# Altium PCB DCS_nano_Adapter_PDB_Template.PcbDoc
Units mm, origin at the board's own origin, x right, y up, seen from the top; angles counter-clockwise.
Board outline 119.55 x 51 mm, 6 copper layers (Top Layer, Layer 2, Layer 3, Layer 4, Layer 5, Bottom Layer), stack 1.74 mm thick; 48 components, 201 nets, 674 pads, 10 vias.
Unrouted connection lines stored in the file: 350.
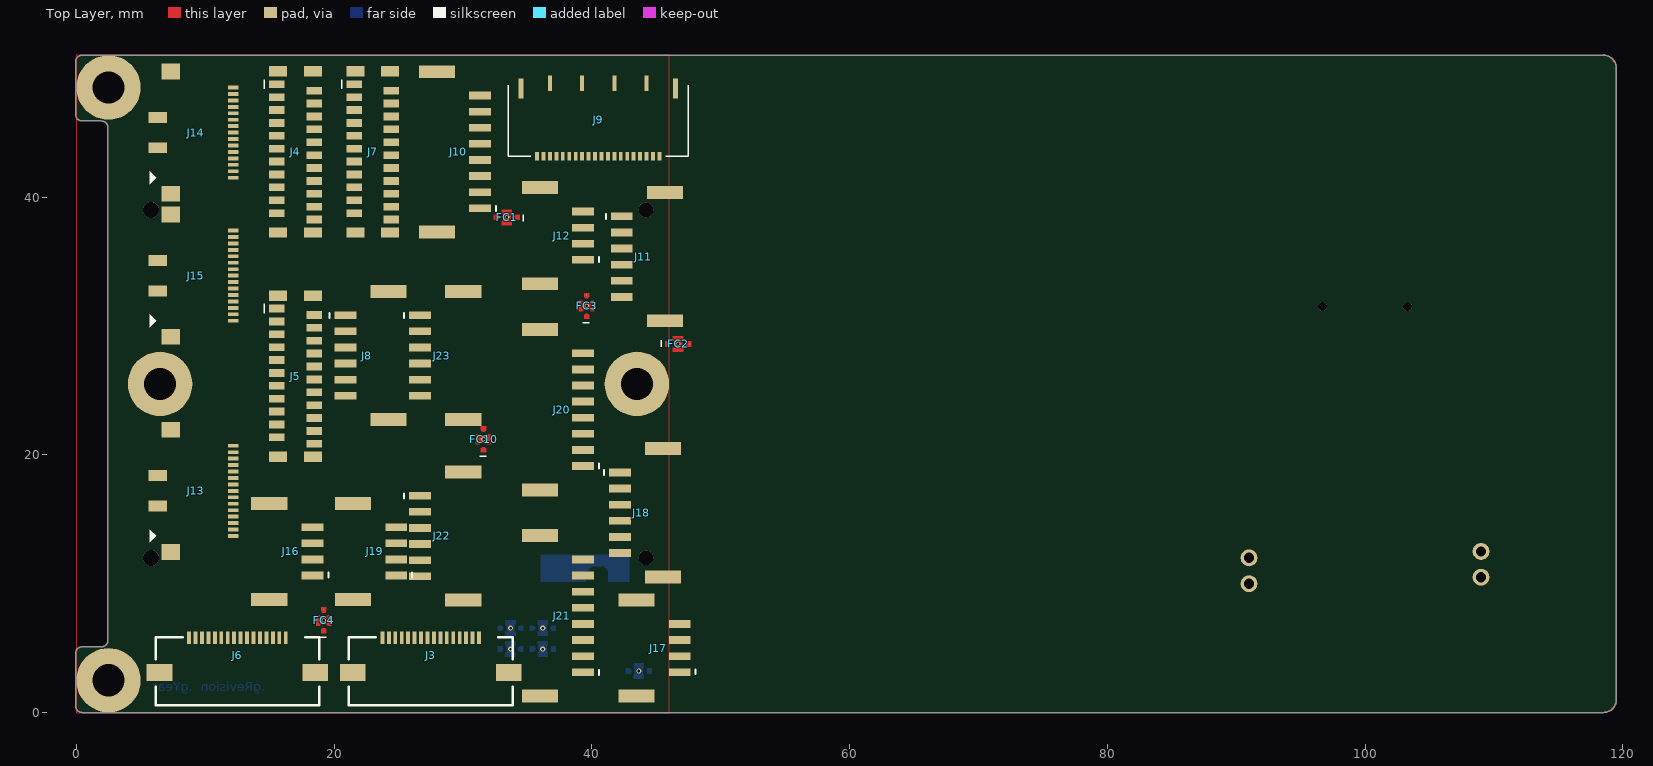
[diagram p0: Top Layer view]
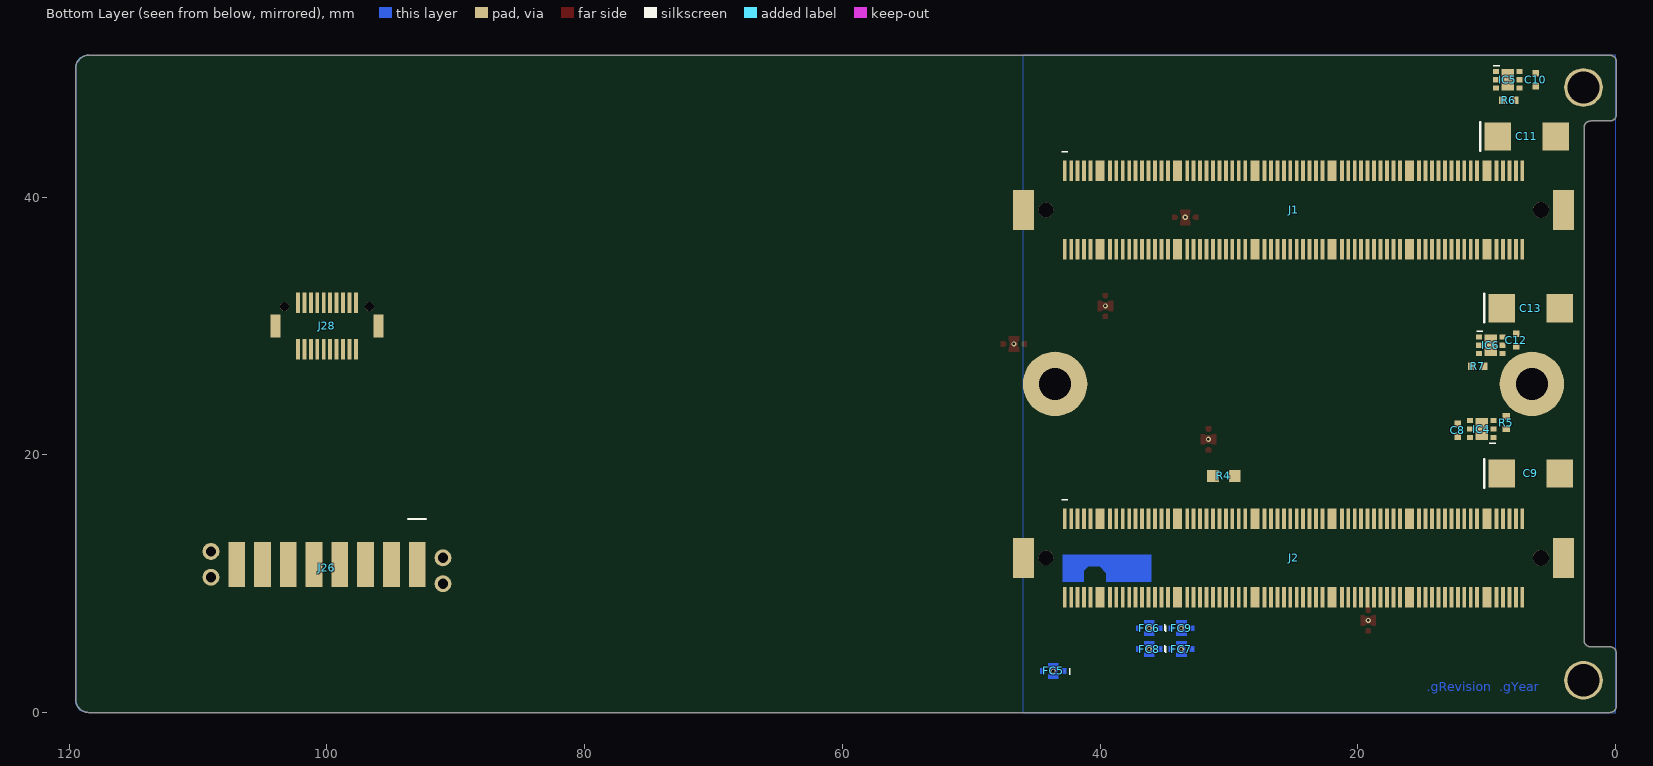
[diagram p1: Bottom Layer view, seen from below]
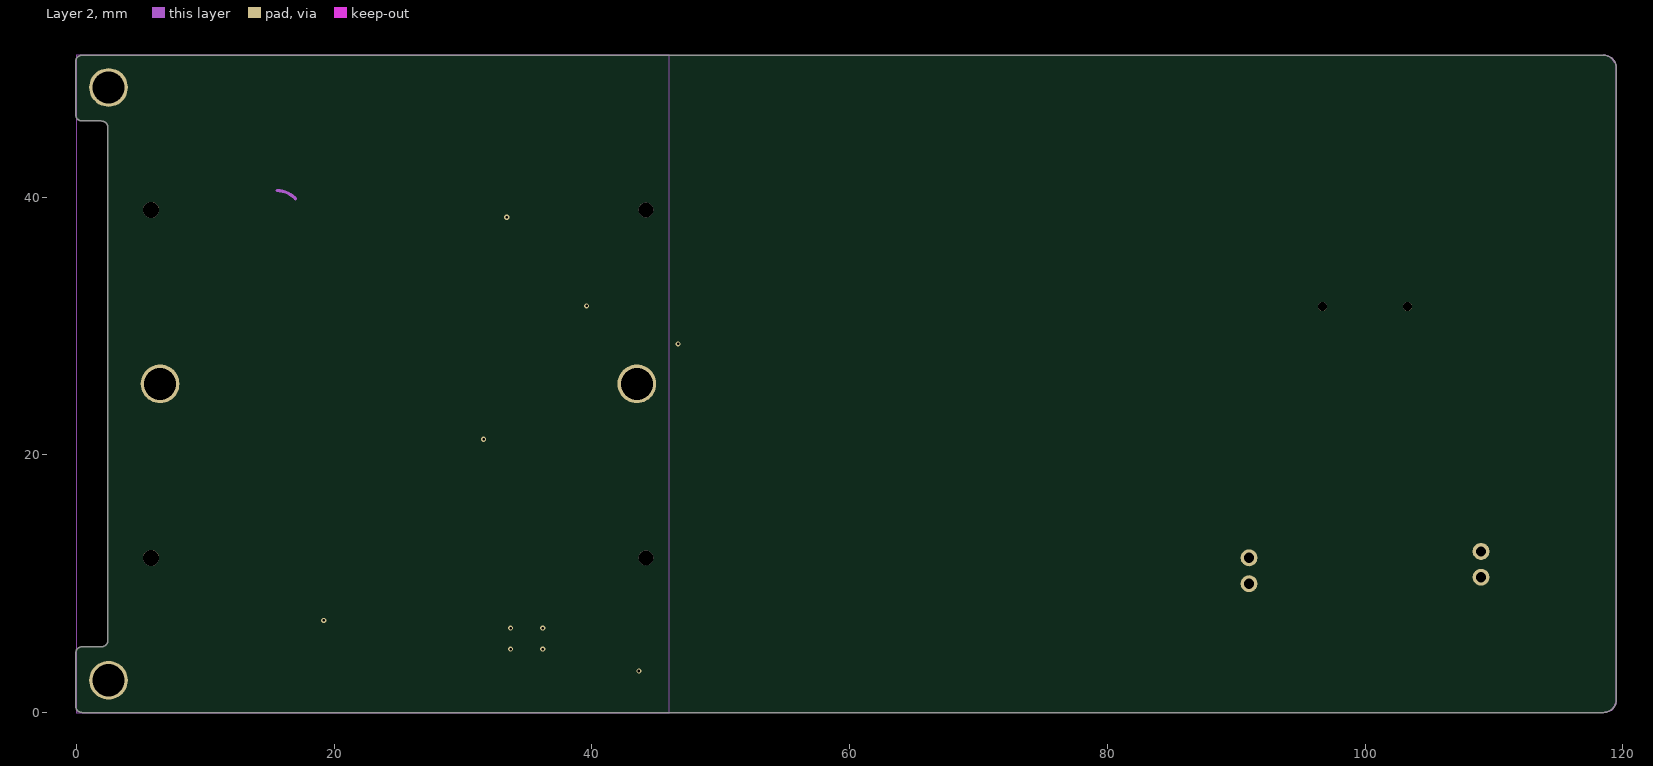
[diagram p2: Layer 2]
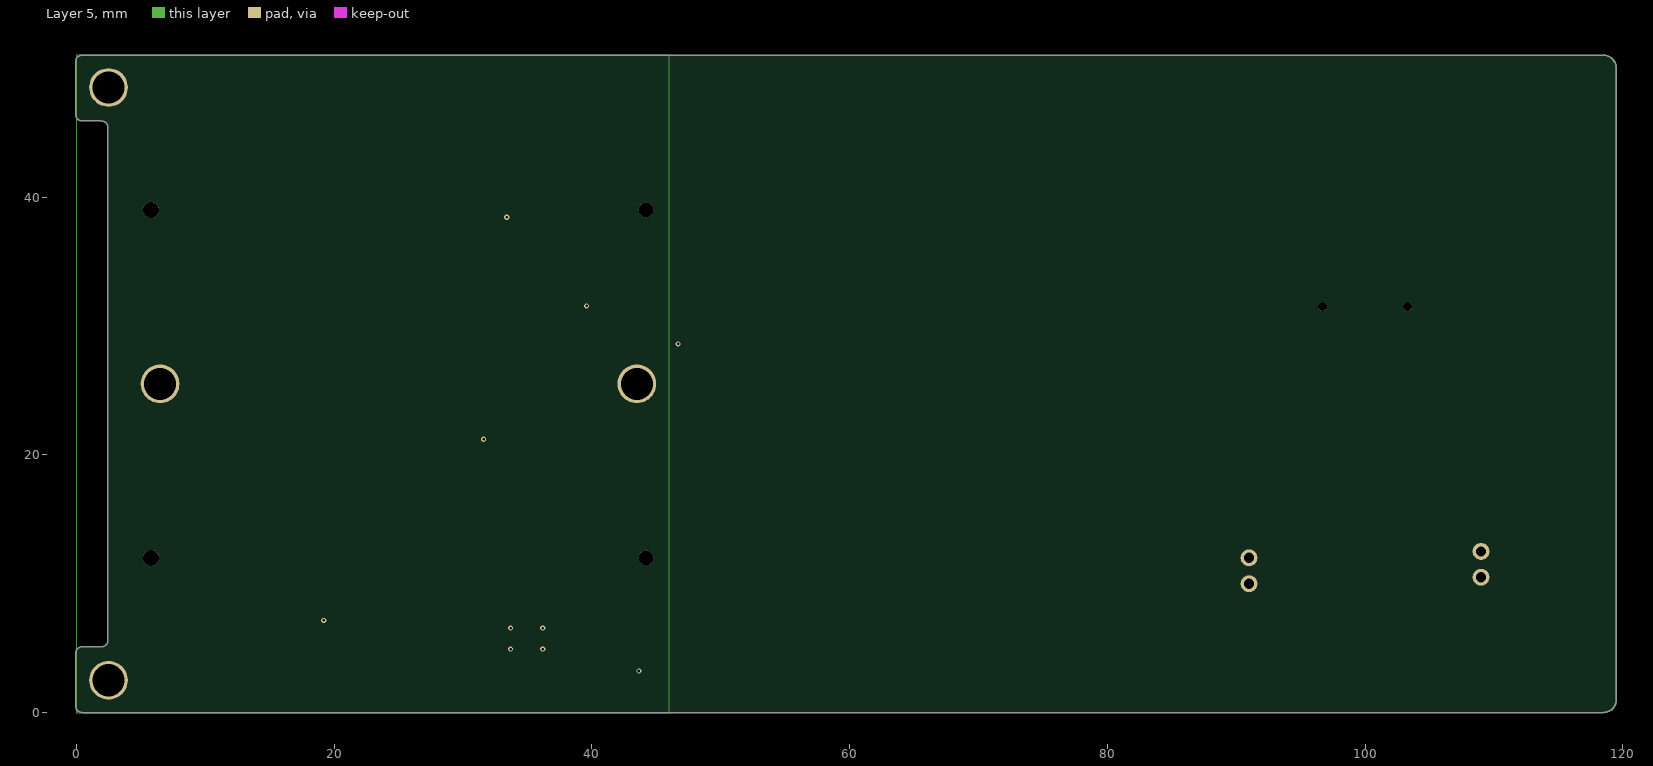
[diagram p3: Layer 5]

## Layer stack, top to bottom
Top Solder: solder mask 0.0102, Solder Resist, Dk 3.5
Top Layer: signal copper 0.035
Dielectric 2: prepreg 0.11, PP, Dk 4.29
Layer 2: signal copper 0.035
Dielectric 4: core 0.6, FR-4, Dk 4.3
Layer 3: signal copper 0.035
Dielectric 1: prepreg 0.11, PP, Dk 4.29
Layer 4: signal copper 0.035
Dielectric 5: core 0.6, FR-4, Dk 4.3
Layer 5: signal copper 0.035
Dielectric 3: prepreg 0.11, PP, Dk 4.29
Bottom Layer: signal copper 0.035
Bottom Solder: solder mask 0.0102, Solder Resist, Dk 3.5

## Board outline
0.45,0 cw(c0.45,0.5) -0.05,0.5 -0.05,4.6 cw(c0.45,4.6) 0.45,5.1 1.95,5.1 ccw(c1.95,5.6) 2.45,5.6 2.45,5.598 2.45,45.4 ccw(c1.95,45.4) 1.95,45.9 0.45,45.9 cw(c0.45,46.4) -0.05,46.4 -0.05,50.5 cw(c0.45,50.5) 0.45,51 1.95,51 118.5,51 cw(c118.5,50) 119.5,50 119.5,1 cw(c118.5,1) 118.5,0

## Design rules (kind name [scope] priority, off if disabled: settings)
Clearance Clearance_GND [InNet('GND')] p1: gap=0.127 ignorepadtopadclearanceinfootprint=TRUE except(0.3: Via-Poly; 0.5: Arc-Poly Track-Poly SMDPad-Poly THPad-Poly Fill-Poly Poly-Poly)
Clearance Clearance_DEfault [All] p2: gap=0.127 ignorepadtopadclearanceinfootprint=TRUE except(0.2: Arc-Poly Track-Poly SMDPad-Poly THPad-Poly Via-Poly Fill-Poly Poly-Poly)
ComponentClearance 3D [OnLayer('Mechanical1')] p1: gap=0 collisioncheckmode=3 verticalgap=0 showdistances=FALSE
ComponentClearance ComponentClearance_HasFootprint('HRS_FX10A-120S/12-SV') [HasFootprint('HRS_FX10A-120S/12-SV')] p2: gap=0 collisioncheckmode=3 verticalgap=0 showdistances=FALSE
ComponentClearance [All] p3: gap=0.254 collisioncheckmode=3 verticalgap=0.254 showdistances=FALSE
DiffPairsRouting 90Ohm_Diffs [InDifferentialPairClass('90OHM_NETS')] p1: maxlimit=0.254 minlimit=0.203 mostfreqgap=0.254 toplayer_mingap=0.24 toplayer_maxgap=0.24 toplayer_prefgap=0.24 toplayer_minwidth=0.2 toplayer_maxwidth=0.2 toplayer_prefwidth=0.2 midlayer3_maxgap=0.203 midlayer3_prefgap=0.203 midlayer3_minwidth=0.127 midlayer3_maxwidth=0.127 midlayer3_prefwidth=0.127 bottomlayer_mingap=0.25 bottomlayer_maxgap=0.25 bottomlayer_prefgap=0.25 bottomlayer_minwidth=0.2 bottomlayer_maxwidth=0.2 bottomlayer_prefwidth=0.2 impedanceprofiledriven=TRUE impedanceprofileid={C9F50B21-FE22-43FD-958F-A5668B17B2B7} impedanceprofilevalue=90.000000 maxuncoupledlength=12.7
DiffPairsRouting 95Ohm_Diffs [InDifferentialPairClass('95OHM_NETS')] p2: maxlimit=0.3 minlimit=0.239 mostfreqgap=0.295 toplayer_maxgap=0.239 toplayer_prefgap=0.239 toplayer_minwidth=0.18 toplayer_maxwidth=0.18 toplayer_prefwidth=0.18 midlayer3_mingap=0.295 midlayer3_maxgap=0.295 midlayer3_minwidth=0.127 midlayer3_maxwidth=0.127 midlayer3_prefwidth=0.127 bottomlayer_maxgap=0.239 bottomlayer_prefgap=0.239 bottomlayer_minwidth=0.18 bottomlayer_maxwidth=0.18 bottomlayer_prefwidth=0.18 impedanceprofiledriven=TRUE impedanceprofileid={FDBBF226-2248-4E26-9AAD-8D10470732B8} impedanceprofilevalue=95.000000 maxuncoupledlength=12.7
MatchedLengths CSI_INTRA [InxSignalClass('xSignals_CSI')] p1: tolerance=0.07 checknetsindiffpair=TRUE checkdiffpairvsdiffpair=FALSE checkxsignals=FALSE checkothers=FALSE
MatchedLengths ETH_INTRA [InxSignalClass('xSignals_ETH')] p2: tolerance=0.05 checknetsindiffpair=TRUE checkdiffpairvsdiffpair=FALSE checkxsignals=FALSE checkothers=FALSE
MatchedLengths PCIE_INTRA [InxSignalClass('xSignals_PCIE')] p3: tolerance=0.04 checknetsindiffpair=TRUE checkdiffpairvsdiffpair=FALSE checkxsignals=FALSE checkothers=FALSE
MatchedLengths USB3_INTRA [InxSignalClass('xSignals_USB3')] p4: tolerance=0.07 checknetsindiffpair=TRUE checkdiffpairvsdiffpair=FALSE checkxsignals=FALSE checkothers=FALSE
MatchedLengths USB2_INTRA [InxSignalClass('xSignals_USB2')] p5: tolerance=0.4 checknetsindiffpair=TRUE checkdiffpairvsdiffpair=FALSE checkxsignals=FALSE checkothers=FALSE
MatchedLengths CSI0_GROUP [InxSignalClass('xSIgnals_CSI0')] p6: tolerance=0.5 checknetsindiffpair=FALSE checkdiffpairvsdiffpair=TRUE checkxsignals=TRUE checkothers=TRUE
MatchedLengths CSI1_GROUP [InxSignalClass('xSIgnals_CSI1')] p7: tolerance=0.5 checknetsindiffpair=FALSE checkdiffpairvsdiffpair=TRUE checkxsignals=TRUE checkothers=TRUE
MatchedLengths CSI2_3_GROUP [InxSignalClass('xSIgnals_CSI_2_3')] p8: tolerance=0.5 checknetsindiffpair=FALSE checkdiffpairvsdiffpair=TRUE checkxsignals=TRUE checkothers=TRUE
MinimumSolderMaskSliver [All] p1: minsoldermaskwidth=0.2
PolygonConnect Polygon_GND_connect [InNet('GND')] p1: thpad.connectstyle=Relief thpad.reliefconductorwidth=0.254 thpad.reliefentries=4 thpad.polygonreliefangle="90 Angle" thpad.airgapwidth=0.254 smdpad.connectstyle=Relief smdpad.reliefconductorwidth=0.2 smdpad.reliefentries=4 smdpad.polygonreliefangle="90 Angle" smdpad.airgapwidth=0.2 via.connectstyle=Direct via.reliefconductorwidth=0.254 via.reliefentries=4 via.polygonreliefangle="90 Angle" via.airgapwidth=0.254
PolygonConnect [All] p2: thpad.connectstyle=Relief thpad.reliefconductorwidth=0.254 thpad.reliefentries=4 thpad.polygonreliefangle="90 Angle" thpad.airgapwidth=0.254 smdpad.connectstyle=Direct smdpad.reliefconductorwidth=0.254 smdpad.reliefentries=4 smdpad.polygonreliefangle="90 Angle" smdpad.airgapwidth=0.254 via.connectstyle=Direct via.reliefconductorwidth=0.254 via.reliefentries=4 via.polygonreliefangle="90 Angle" via.airgapwidth=0.254
RoutingVias [All] p1: holewidth=0.2 width=0.4 viastyle="Through Hole" minholewidth=0.2 minwidth=0.4 maxholewidth=0.6 maxwidth=0.9
SilkToSilkClearance [All] p1: silktosilkclearance=0
SilkToSolderMaskClearance [IsPad] p1: minsilkscreentomaskgap=0.01 clearancetoexposedcopper=TRUE
SolderMaskExpansion [All] p1: expansion=0.102 istentingtop=FALSE
SupplyNets "Schematic Supply Nets_7" [InNet('5V_CRUCIAL')] p1: voltage=0.000
SupplyNets "Schematic Supply Nets_6" [InNet('5V')] p2: voltage=0.000
SupplyNets "Schematic Supply Nets_5" [InNet('5V_SAFETY')] p3: voltage=0.000
SupplyNets "Schematic Supply Nets_4" [InNet('3V3')] p4: voltage=0.000
SupplyNets "Schematic Supply Nets_3" [InNet('3V3_SOM')] p5: voltage=0.000
SupplyNets "Schematic Supply Nets_2" [InNet('GND')] p6: voltage=0.000
SupplyNets "Schematic Supply Nets_1" [InNet('5V_PERIPH')] p7: voltage=0.000
SupplyNets "Schematic Supply Nets" [InNet('VDD_SOM')] p8: voltage=0.000
Width [All] p1: maxlimit=0.8 minlimit=0.127 preferedwidth=0.254
25 further rules are at their usual default settings.

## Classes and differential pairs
component class U_PDB_Related_Connectors: J26 J28
differential pair class 95OHM_NETS: ETH1A ETH1B ETH1C ETH1D ETH2A ETH2B ETH2C ETH2D
differential pair class 90OHM_NETS: CSI0_CLK CSI0_D0 CSI0_D1 CSI1_CLK CSI1_D0 CSI1_D1 CSI2_CLK CSI2_D0 CSI2_D1 CSI3_CLK CSI3_D0 CSI3_D1 PCIE_AD_CLK PCIE_AD_RX PCIE_AD_TX USB_0 USB_1 USB_2 USBSS0_RX USBSS0_TX USBSS1_RX USBSS1_TX USBSS2_RX USBSS2_TX
net class USB_NETS: USB_0_N USB_0_P USB_1_N USB_1_P USB_2_N USB_2_P USBSS0_RX_N USBSS0_RX_P USBSS0_TX_N USBSS0_TX_P USBSS1_RX_N USBSS1_RX_P USBSS1_TX_N USBSS1_TX_P USBSS2_RX_N USBSS2_RX_P USBSS2_TX_N USBSS2_TX_P
net class PCIE_NETS: PCIE_AD_CLK_N PCIE_AD_CLK_P PCIE_AD_RX_N PCIE_AD_RX_P PCIE_AD_TX_N PCIE_AD_TX_P
net class ETH_NETS: ETH1A_N ETH1A_P ETH1B_N ETH1B_P ETH1C_N ETH1C_P ETH1D_N ETH1D_P ETH2A_N ETH2A_P ETH2B_N ETH2B_P ETH2C_N ETH2C_P ETH2D_N ETH2D_P
net class CSI_NETS: CSI0_CLK_N CSI0_CLK_P CSI0_D0_N CSI0_D0_P CSI0_D1_N CSI0_D1_P CSI1_CLK_N CSI1_CLK_P CSI1_D0_N CSI1_D0_P CSI1_D1_N CSI1_D1_P CSI2_CLK_N CSI2_CLK_P CSI2_D0_N CSI2_D0_P CSI2_D1_N CSI2_D1_P CSI3_CLK_N CSI3_CLK_P CSI3_D0_N CSI3_D0_P CSI3_D1_N CSI3_D1_P
net class CAN_NETS: CAN_1_N CAN_1_P CAN_2_N CAN_2_P CAN_3_N CAN_3_P CAN_JET_N CAN_JET_P
component class U_Jetson_Connectors: C8 C9 C10 C11 C12 C13 FC1 FC2 FC3 IC4 IC5 IC6 J3 J4 J5 J6 J7 J8 J9 J10 J11 J12 J13 J14 J15 R4 R5 R6 R7
component class U_FMU_related_Connectors: FC4 FC5 FC6 FC7 FC8 FC9 FC10 J16 J17 J18 J19 J20 J21 J22 J23
component class U_Adapter_B2B_Connectors: J1 J2
differential pair USBSS2_TX: +USBSS2_TX_P -USBSS2_TX_N
differential pair USBSS2_RX: +USBSS2_RX_P -USBSS2_RX_N
differential pair USBSS1_TX: +USBSS1_TX_P -USBSS1_TX_N
differential pair USBSS1_RX: +USBSS1_RX_P -USBSS1_RX_N
differential pair USBSS0_TX: +USBSS0_TX_P -USBSS0_TX_N
differential pair USBSS0_RX: +USBSS0_RX_P -USBSS0_RX_N
differential pair USB_2: +USB_2_P -USB_2_N
differential pair USB_1: +USB_1_P -USB_1_N
differential pair USB_0: +USB_0_P -USB_0_N
differential pair PCIE_AD_TX: +PCIE_AD_TX_P -PCIE_AD_TX_N
differential pair PCIE_AD_RX: +PCIE_AD_RX_P -PCIE_AD_RX_N
differential pair PCIE_AD_CLK: +PCIE_AD_CLK_P -PCIE_AD_CLK_N
differential pair ETH2D: +ETH2D_P -ETH2D_N
differential pair ETH2C: +ETH2C_P -ETH2C_N
differential pair ETH2B: +ETH2B_P -ETH2B_N
differential pair ETH2A: +ETH2A_P -ETH2A_N
differential pair ETH1D: +ETH1D_P -ETH1D_N
differential pair ETH1C: +ETH1C_P -ETH1C_N
differential pair ETH1B: +ETH1B_P -ETH1B_N
differential pair ETH1A: +ETH1A_P -ETH1A_N
differential pair CSI3_D1: +CSI3_D1_P -CSI3_D1_N
differential pair CSI3_D0: +CSI3_D0_P -CSI3_D0_N
differential pair CSI3_CLK: +CSI3_CLK_P -CSI3_CLK_N
differential pair CSI2_D1: +CSI2_D1_P -CSI2_D1_N
differential pair CSI2_D0: +CSI2_D0_P -CSI2_D0_N
differential pair CSI2_CLK: +CSI2_CLK_P -CSI2_CLK_N
differential pair CSI1_D1: +CSI1_D1_P -CSI1_D1_N
differential pair CSI1_D0: +CSI1_D0_P -CSI1_D0_N
differential pair CSI1_CLK: +CSI1_CLK_P -CSI1_CLK_N
differential pair CSI0_D1: +CSI0_D1_P -CSI0_D1_N
differential pair CSI0_D0: +CSI0_D0_P -CSI0_D0_N
differential pair CSI0_CLK: +CSI0_CLK_P -CSI0_CLK_N
differential pair CAN_JET: +CAN_JET_P -CAN_JET_N
differential pair CAN_3: +CAN_3_P -CAN_3_N
differential pair CAN_2: +CAN_2_P -CAN_2_N
differential pair CAN_1: +CAN_1_P -CAN_1_N

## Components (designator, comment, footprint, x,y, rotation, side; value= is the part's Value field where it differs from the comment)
C8 "AV_CAP_0402_1uF_25V" C0402 12.25,21.9 r90 bottom value=1uF
C9 "AV_CAP_2312_TANTAL_220uF_25V" AVX-TAJ-C-2_L 6.6,18.55 r180 bottom value=220uF
C10 "AV_CAP_0402_1uF_25V" C0402 6.2,49.1 r270 bottom value=1uF
C11 "AV_CAP_2312_TANTAL_220uF_25V" AVX-TAJ-C-2_L 6.9,44.7 r180 bottom value=220uF
C12 "AV_CAP_0402_1uF_25V" C0402 7.7,28.9 r270 bottom value=1uF
C13 "AV_CAP_2312_TANTAL_220uF_25V" AVX-TAJ-C-2_L 6.6,31.375 r180 bottom value=220uF
FC1 "CMP-023-000005-1" NFM18PS105R0J3D 33.4,38.425 r180 top
FC2 "CMP-023-000005-1" NFM18PS105R0J3D 46.7,28.6 r0 top
FC3 "CMP-023-000005-1" NFM18PS105R0J3D 39.6,31.55 r90 top
FC4 "CMP-023-000005-1" NFM18PS105R0J3D 19.2,7.15 r90 top
FC5 "CMP-023-000005-1" NFM18PS105R0J3D 43.65,3.225 r0 bottom
FC6 "CMP-023-000005-1" NFM18PS105R0J3D 36.2,6.55 r0 bottom
FC7 "CMP-023-000005-1" NFM18PS105R0J3D 33.7,4.925 r180 bottom
FC8 "CMP-023-000005-1" NFM18PS105R0J3D 36.2,4.925 r0 bottom
FC9 "CMP-023-000005-1" NFM18PS105R0J3D 33.7,6.55 r180 bottom
FC10 "CMP-023-000005-1" NFM18PS105R0J3D 31.6,21.2 r90 top
IC4 "CMP-045-000045-1" SON65P200X200X55-7N 10.4,22 r0 bottom
IC5 "CMP-045-000045-1" SON65P200X200X55-7N 8.385,49.1 r180 bottom
IC6 "CMP-045-000045-1" SON65P200X200X55-7N 9.7,28.5 r180 bottom
J1 "CMP-011-000018-1" HRS_FX10A-120S/12-SV 25,39 r180 bottom locked
J2 "CMP-011-000018-1" HRS_FX10A-120S/12-SV 25,12 r180 bottom locked
J3 "CMP-008-000009-1" 5051101692 27.5,3.2 r0 top locked
J4 "CMP-008-000016-1" 5019512210 17,43.5 r270 top
J5 "CMP-008-000016-1" 5019512210 17,26.1 r270 top
J6 "CMP-008-000009-1" 5051101692 12.5,3.2 r0 top locked
J7 "CMP-008-000016-1" 5019512210 23,43.5 r270 top
J8 "BM06B-GHS-TBT(LF)(SN)" FP-BM06B-GHS-TBT_LF_SN-MFG 23.2,27.7 r270 top
J9 "FH41-20S-0.5SH_05_" FH4120S05SH05 40.5,46 r180 top
J10 "BM08B-GHS-TBT(LF)(SN)" FP-BM08B-GHS-TBT_LF_SN-MFG 29,43.5 r270 top
J11 "BM06B-GHS-TBT(LF)(SN)" FP-BM06B-GHS-TBT_LF_SN-MFG 44.65,35.375 r270 top
J12 "BM04B-GHS-TBT(LF)(SN)" FP-BM04B-GHS-TBT_LF_SN-MFG 37,37 r270 top
J13 "CMP-009-000000-1" 5022441530 9.4,17.2 r270 top
J14 "CMP-009-000000-1" 5022441530 9.4,45 r270 top
J15 "CMP-009-000000-1" 5022441530 9.4,33.9 r270 top
J16 "BM04B-GHS-TBT(LF)(SN)" FP-BM04B-GHS-TBT_LF_SN-MFG 16,12.5 r270 top
J17 "BM04B-GHS-TBT(LF)(SN)" FP-BM04B-GHS-TBT_LF_SN-MFG 44.5,5 r270 top
J18 "BM06B-GHS-TBT(LF)(SN)" FP-BM06B-GHS-TBT_LF_SN-MFG 44.5,15.5 r270 top
J19 "BM04B-GHS-TBT(LF)(SN)" FP-BM04B-GHS-TBT_LF_SN-MFG 22.5,12.5 r270 top
J20 "BM08B-GHS-TBT(LF)(SN)" FP-BM08B-GHS-TBT_LF_SN-MFG 37,23.5 r270 top
J21 "BM08B-GHS-TBT(LF)(SN)" FP-BM08B-GHS-TBT_LF_SN-MFG 37,7.5 r270 top
J22 "BM06B-GHS-TBT(LF)(SN)" FP-BM06B-GHS-TBT_LF_SN-MFG 29,13.7 r270 top
J23 "BM06B-GHS-TBT(LF)(SN)" FP-BM06B-GHS-TBT_LF_SN-MFG 29,27.7 r270 top
J26 "UMPS-08-03.5-G-V-S-W-TR" SAMTEC_UMPS-08-03.5-G-V-S-W-TR 100,11.5 r0 bottom locked
J28 "CMP-011-000020-1" 10132797-025100LF 100,30 r180 bottom locked
R4 "AV_RES_0603_120R_1%" R0603 30.4,18.356 r0 bottom value=120R
R5 "AV_RES_0402_18k_1%" R0402 8.5,22.5 r270 bottom value=18k
R6 "AV_RES_0402_18k_1%" R0402 8.3,47.5 r0 bottom value=18k
R7 "AV_RES_0402_18k_1%" R0402 10.7,26.875 r0 bottom value=18k

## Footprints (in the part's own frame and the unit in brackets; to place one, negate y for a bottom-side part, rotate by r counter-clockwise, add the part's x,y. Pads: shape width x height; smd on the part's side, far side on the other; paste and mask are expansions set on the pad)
10132797-025100LF [mm]
  rect 0.3x1.6 smd: 1(2.25,1.8) 2(1.75,1.8) 3(1.25,1.8) 4(0.75,1.8) 5(0.25,1.8) 6(-0.25,1.8) 7(-0.75,1.8) 8(-1.25,1.8) 9(-1.75,1.8) 10(-2.25,1.8) 11(-2.25,-1.8) 12(-1.75,-1.8) 13(-1.25,-1.8) 14(-0.75,-1.8) 15(-0.25,-1.8) 16(0.25,-1.8) 17(0.75,-1.8) 18(1.25,-1.8) 19(1.75,-1.8) 20(2.25,-1.8)
  round 0.7 hole 0.7 unplated: LOC(-3.3,1.5) LOC(3.3,1.5)
  rect 0.8x1.8 smd: MP(-4,0) MP(4,0)
  body extent -4,-2.29 4,2.31, height 4.3
5019512210 [mm]
  rect 0.6x1.2 smd: 1(-5.25,-1.45) 2(-4.75,1.45) 3(-4.25,-1.45) 4(-3.75,1.45) 5(-3.25,-1.45) 6(-2.75,1.45) 7(-2.25,-1.45) 8(-1.75,1.45) 9(-1.25,-1.45) 10(-0.75,1.45) 11(-0.25,-1.45) 12(0.25,1.45) 13(0.75,-1.45) 14(1.25,1.45) 15(1.75,-1.45) 16(2.25,1.45) 17(2.75,-1.45) 18(3.25,1.45) 19(3.75,-1.45) 20(4.25,1.45) 21(4.75,-1.45) 22(5.25,1.45)
  rect 0.8x1.4 smd: MP1(-6.25,-1.35) MP2(6.25,-1.35) MP3(6.25,1.35) MP4(-6.25,1.35)
  silkscreen extent -5.6,-2.4 -4.9,-2.4, body extent -6.9,-2.05 6.9,2.08, height 4.59
5022441530 [mil] "Molex LVDS conn, 15pin, 0.5mm pitch"
  rect 11.81x31.5 smd: 1(-137.8,109.45) 2(-118.11,109.45) 3(-98.43,109.45) 4(-78.74,109.45) 5(-59.06,109.45) 6(-39.37,109.45) 7(-19.69,109.45) 8(0,109.45) 9(19.69,109.45) 10(39.37,109.45) 11(59.06,109.45) 12(78.74,109.45) 13(98.43,109.45) 14(118.11,109.45) 15(137.8,109.45)
  rect 48.03x55.12 smd: MP1(-186.61,-81.5) MP2(186.61,-81.5)
  rect 33.46x55.12 smd: MP3(-46.26,-121.26) MP4(46.26,-121.26)
  silkscreen extent 118,-146 157,-126, body extent -199,-138 199,116, height 92
5051101692 [mm]
  rect 0.3x1 smd: 1(-3.75,2.6) 2(-3.25,2.6) 3(-2.75,2.6) 4(-2.25,2.6) 5(-1.75,2.6) 6(-1.25,2.6) 7(-0.75,2.6) 8(-0.25,2.6) 9(0.25,2.6) 10(0.75,2.6) 11(1.25,2.6) 12(1.75,2.6) 13(2.25,2.6) 14(2.75,2.6) 15(3.25,2.6) 16(3.75,2.6)
  rect 2x1.3 smd: MP1(-6.05,-0.1) MP2(6.05,-0.1)
  silkscreen extent -6.35,-2.65 6.35,2.65, body extent -6.75,-2.43 6.75,2.87, height 1.9
AVX-TAJ-C-2_L [mm] "Molded Capacitor, 2-Leads, Body 6.2x3.4mm, IPC High Density"
  rect 2.05x2.2 smd: +(-2.25,0) -(2.25,0)
  silkscreen extent -3.6,-1.1 -3.6,1.1, body extent -3.32,-1.7 3.32,1.7, height 2.8
C0402 [mm]
  rect 0.5x0.5 smd: 1(-0.5,0) 2(0.5,0)
  body extent -0.5,-0.25 0.5,0.25, height 0.5
FH4120S05SH05 [mm]
  rect 0.3x0.65 smd: 1(-4.75,2.838) 2(-4.25,2.838) 3(-3.75,2.838) 4(-3.25,2.838) 5(-2.75,2.838) 6(-2.25,2.838) 7(-1.75,2.838) 8(-1.25,2.838) 9(-0.75,2.838) 10(-0.25,2.838) 11(0.25,2.838) 12(0.75,2.838) 13(1.25,2.838) 14(1.75,2.838) 15(2.25,2.838) 16(2.75,2.838) 17(3.25,2.838) 18(3.75,2.838) 19(4.25,2.838) 20(4.75,2.838)
  rect 0.4x1.55 smd: MP1(-6,-2.412) MP2(6,-2.412)
  rect 0.3x1.2 smd: MP3(-3.75,-2.837) MP4(1.25,-2.837) MP5(3.75,-2.837) MP6(-1.25,-2.837)
  silkscreen extent -7,-2.66 7,2.84, body extent -7,-3.25 7,3, height 2.48
FP-BM04B-GHS-TBT_LF_SN-MFG [mm]
  rect 0.6x1.7 smd paste+0 mask+0: 1(1.875,2.325) 2(0.625,2.325) 3(-0.625,2.325) 4(-1.875,2.325)
  rect 1x2.8 smd paste+0 mask+0: GND(-3.725,-1.025) GND(3.725,-1.025)
  silkscreen extent 1.65,3.56 2.03,3.56, body extent -4.33,-2.52 4.33,3.27, height 0.25
FP-BM06B-GHS-TBT_LF_SN-MFG [mm]
  rect 0.6x1.7 smd paste+0 mask+0: 1(-3.125,-2.325) 2(-1.875,-2.325) 3(-0.625,-2.325) 4(0.625,-2.325) 5(1.875,-2.325) 6(3.125,-2.325)
  rect 1x2.8 smd paste+0 mask+0: GND(-4.975,1.025) GND(4.975,1.025)
  silkscreen extent -3.3,-3.56 -2.92,-3.56, body extent -5.58,-3.27 5.58,2.52, height 0.25
FP-BM08B-GHS-TBT_LF_SN-MFG [mm]
  rect 0.6x1.7 smd paste+0 mask+0: 1(4.375,2.325) 2(3.125,2.325) 3(1.875,2.325) 4(0.625,2.325) 5(-0.625,2.325) 6(-1.875,2.325) 7(-3.125,2.325) 8(-4.375,2.325)
  rect 1x2.8 smd paste+0 mask+0: GND(-6.225,-1.025) GND(6.225,-1.025)
  silkscreen extent 4.19,3.56 4.57,3.56, body extent -6.63,-2.12 6.63,2.83, height 4.05
HRS_FX10A-120S/12-SV [mm]
  rect 0.3x1.6 smd paste-2: 1(-17.75,3.05) 2(-17.75,-3.05) 3(-17.25,3.05) 4(-17.25,-3.05) 5(-16.75,3.05) 6(-16.75,-3.05) 7(-16.25,3.05) 8(-16.25,-3.05) 9(-15.75,3.05) 10(-15.75,-3.05) 11(-14.25,3.05) 12(-14.25,-3.05) 13(-13.75,3.05) 14(-13.75,-3.05) 15(-13.25,3.05) 16(-13.25,-3.05) 17(-12.75,3.05) 18(-12.75,-3.05) 19(-12.25,3.05) 20(-12.25,-3.05) 21(-11.75,3.05) 22(-11.75,-3.05) 23(-11.25,3.05) 24(-11.25,-3.05) 25(-10.75,3.05) 26(-10.75,-3.05) 27(-10.25,3.05) 28(-10.25,-3.05) 29(-9.75,3.05) 30(-9.75,-3.05) 31(-8.25,3.05) 32(-8.25,-3.05) 33(-7.75,3.05) 34(-7.75,-3.05) 35(-7.25,3.05) 36(-7.25,-3.05) 37(-6.75,3.05) 38(-6.75,-3.05) 39(-6.25,3.05) 40(-6.25,-3.05) 41(-5.75,3.05) 42(-5.75,-3.05) 43(-5.25,3.05) 44(-5.25,-3.05) 45(-4.75,3.05) 46(-4.75,-3.05) 47(-4.25,3.05) 48(-4.25,-3.05) 49(-3.75,3.05) 50(-3.75,-3.05) 51(-2.25,3.05) 52(-2.25,-3.05) 53(-1.75,3.05) 54(-1.75,-3.05) 55(-1.25,3.05) 56(-1.25,-3.05) 57(-0.75,3.05) 58(-0.75,-3.05) 59(-0.25,3.05) 60(-0.25,-3.05) 61(0.25,3.05) 62(0.25,-3.05) 63(0.75,3.05) 64(0.75,-3.05) 65(1.25,3.05) 66(1.25,-3.05) 67(1.75,3.05) 68(1.75,-3.05) 69(2.25,3.05) 70(2.25,-3.05) 71(3.75,3.05) 72(3.75,-3.05) 73(4.25,3.05) 74(4.25,-3.05) 75(4.75,3.05) 76(4.75,-3.05) 77(5.25,3.05) 78(5.25,-3.05) 79(5.75,3.05) 80(5.75,-3.05) 81(6.25,3.05) 82(6.25,-3.05) 83(6.75,3.05) 84(6.75,-3.05) 85(7.25,3.05) 86(7.25,-3.05) 87(7.75,3.05) 88(7.75,-3.05) 89(8.25,3.05) 90(8.25,-3.05) 91(9.75,3.05) 92(9.75,-3.05) 93(10.25,3.05) 94(10.25,-3.05) 95(10.75,3.05) 96(10.75,-3.05) 97(11.25,3.05) 98(11.25,-3.05) 99(11.75,3.05) 100(11.75,-3.05) 101(12.25,3.05) 102(12.25,-3.05) 103(12.75,3.05) 104(12.75,-3.05) 105(13.25,3.05) 106(13.25,-3.05) 107(13.75,3.05) 108(13.75,-3.05) 109(14.25,3.05) 110(14.25,-3.05) 111(15.75,3.05) 112(15.75,-3.05) 113(16.25,3.05) 114(16.25,-3.05) 115(16.75,3.05) 116(16.75,-3.05) 117(17.25,3.05) 118(17.25,-3.05) 119(17.75,3.05) 120(17.75,-3.05)
  rect 0.7x1.6 smd paste-2: MP1(-15,3.05) MP2(-15,-3.05) MP3(-9,3.05) MP4(-9,-3.05) MP5(-3,3.05) MP6(-3,-3.05) MP7(3,3.05) MP8(3,-3.05) MP9(9,3.05) MP10(9,-3.05) MP11(15,3.05) MP12(15,-3.05)
  rect 1.6x3.1 smd: MP13(-20.95,0) MP14(20.95,0)
  round 1.15 hole 1.15 unplated: ""(-19.2,0)
  round 1.25 hole 1.25 unplated: ""(19.2,0)
  silkscreen extent -18,4.5 -17.5,4.5, body extent -21.55,-3.65 21.55,3.65, height 3.32
NFM18PS105R0J3D [mil]
  round 1 smd: 1(-33.46,0) 2(33.46,0)
  round 1 smd mask+4: GND(0,0)
  Top Layer region: 11.81,7.87 15.75,11.81 15.75,23.62 -15.75,23.62 -15.75,11.81 -11.81,7.87 -11.81,-7.87 -15.75,-11.81 -15.75,-23.62 15.75,-23.62 15.75,-11.81 11.81,-7.87
  Top Layer region: 27.56,7.87 23.62,3.94 23.62,3.94 23.62,-3.94 27.56,-7.87 39.37,-7.87 39.37,7.87
  Top Layer region: -27.56,-7.87 -23.62,-3.94 -23.62,3.94 -23.62,3.94 -27.56,7.87 -39.37,7.87 -39.37,-7.87 -39.37,-7.87
  silkscreen extent -51,-8 -51,12, body extent -31,-16 31,16, height 24
R0402 [mm] "AE-R0402"
  rect 0.5x0.6 smd: 1(-0.5,0) 2(0.5,0)
  body extent -0.58,-0.27 0.57,0.28, height 0.41
R0603 [mm] "AE-R0603"
  rect 0.9x0.9 smd: 1(-0.85,0) 2(0.85,0)
  body extent -0.85,-0.4 0.85,0.4, height 0.56
SAMTEC_UMPS-08-03.5-G-V-S-W-TR [mm]
  rect 1.3x3.5 smd: 01(-7,0) 02(-5,0) 03(-3,0) 04(-1,0) 05(1,0) 06(3,0) 07(5,0) 08(7,0)
  round 1.308 hole 0.8: S1(-9,1.5) S2(9,1) S3(-9,-0.5) S4(9,-1)
  silkscreen extent -7.7,-3.5 -6.3,-3.5, body extent -10.55,-3.45 10.5,3.54, height 4.15
SON65P200X200X55-7N [mm]
  rect 0.47x0.4 smd: 1(-0.915,0.65) 2(-0.915,0) 3(-0.915,-0.65) 4(0.915,-0.65) 5(0.915,0) 6(0.915,0.65)
  rect 0.95x1.7 smd: 7(0,0)
  silkscreen extent -1.1,1.1 -0.6,1.1, body extent -1.05,-1 1.05,1, height 0.55

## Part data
C8 C10 C12: library part CMP-001-00083-2, "CAP 1uF 25V ±10% case 0402(1005 metric) Thickness 1mm SMD", Tolerance=±10%, Voltage=25V
C9 C11 C13: library part CMP-023-000006-2, "CAP Standard Tantalum,  220uF, 25V, +/- 10%,  6023 (2312 inch) case, SMD", Voltage=25V
FC1 FC2 FC3 FC4 FC5 FC6 FC7 FC8 FC9 FC10: "Capacitor, Filter, 1uF, 6.3V, 2A, 0603, SMD", Manufacturer_Name=Murata, Manufacturer_Part_Number=NFM18PS105R0J3D
IC4 IC5 IC6: "Adjustable Current‐Limiting Power‐Distribution Switches, NCP380L= enable Low / H= enable high", Manufacturer_Name=onsemi, Manufacturer_Part_Number=NCP380HMUAJAATBG, Maximum_Temperature=+85, Minimum_Temperature=-40
J1 J2: "120 Position Connector Receptacle, Center Strip Contacts Surface Mount Gold", Manufacturer_Name="Hirose Electric Co Ltd", Manufacturer_Part_Number=FX10A-120S/12-SV
J3 J6: "Connector", Manufacturer_Name=Molex, Manufacturer_Part_Number=505110-1692
J4 J5 J7: "Molex 501951 Series 0.5mm Pitch 22 Way SMT Female FPC Connector", Manufacturer_Name=Molex, Manufacturer_Part_Number=501951-2210/501951-2210
J8 J11 J18 J22 J23: library part CMP-00002-2, "Connector Header, GH Series, 6 Position, 1.25mm, 50V, Surface Mount, Locking Ramp, Natural", Manufacturer_Name=JST
J9: library part CMP-008-000015-1, "Connector", Manufacturer_Name=Hirose, Manufacturer_Part_Number=FH41-20S-0.5SH(05)
J10 J20 J21: library part CMP-00003-2, "Connector Header, GH Series, 8 Position, 1.25mm, 50V, Surface Mount, Locking Ramp, Natural", Manufacturer_Name=JST
J12 J16 J17 J19: library part CMP-00000-3, "Connector Header, GH Series, 4 Position, 1.25mm, 50V, Surface Mount, Locking Ramp, Natural", Manufacturer_Name=JST
J13 J14 J15: "FFC & FPC Connectors 0.5 FFC For LVDS Ass ssy 15Ckt EmbsTp pkg", Manufacturer_Name=Molex, Manufacturer_Part_Number=502244-1530
J26: library part CMP-013-000042-1, "Power to the Board", Manufacturer_Name=Samtec
J28: "BergStak® 0.5mm Mezzanine Connector", Manufacturer_Name=Amphenol, Manufacturer_Part_Number=10132797-025100LF
R4: library part CMP-009-00181-1, "RES 120R ±1% case 0603(1608 metric) Thickness 1mm SMD", Case/Package=0603, Tolerance=1%
R5 R6 R7: library part CMP-009-00178-2, "RES 18k ±1% case 0402(1005 metric) Thickness 1mm SMD", Case/Package=0402, Power Rating=100mW, Tolerance=1%

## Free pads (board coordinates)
  round 5 / inner round 3 / far side round 3 hole 2.5 unplated mask+0.102: 1(2.5,2.5) 1(2.5,48.5)
  round 5 / inner round 3 / far side round 5 hole 2.5 unplated mask+0.102: 1(6.5,25.5) 2(43.5,25.5)

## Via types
v1: diameter 0.4, hole 0.2, Top Layer to Bottom Layer, tented both sides, 10 vias

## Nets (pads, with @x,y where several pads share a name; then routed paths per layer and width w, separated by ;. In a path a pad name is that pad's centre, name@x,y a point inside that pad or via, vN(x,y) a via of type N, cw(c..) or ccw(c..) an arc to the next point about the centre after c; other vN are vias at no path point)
3V3: J4.1 J5.1 J7.1 J9.16 J9.17 J9.18 J9.19 J9.20
3V3_SOM: J26.03
5V: C8.1 C10.1 C12.1 FC1.1 FC2.1 FC3.1 FC4.1 FC5.1 FC6.1 FC7.1 FC8.1 FC9.1 FC10.1 IC4.6 IC5.6 IC6.6 J3.15 J3.16 J6.15 J6.16
5V_CRUCIAL: J26.02
5V_PERIPH: J26.01
5V_SAFETY: J26.06
ADD_BUF_OE: J2.28
BUF_FMU_CS: J2.34
BUF_FMU_MISO: J2.30
BUF_FMU_MOSI: J2.32
BUF_FMU_SCK: J2.24
BUF_FMU_U1_RX_SPECT: J2.38
BUF_FMU_U1_TX: J2.36
CAM_I2C_SCL: J1.29 J4.3
CAM_I2C_SDA: J1.31 J4.2
CAM_MCLK_0: J1.120
CAM_MCLK_1: J1.119
CAM_MCLK_2: J1.75
CAN_1_N: J2.51 J19.3
CAN_1_P: J2.53 J19.2
CAN_2_N: J2.47 J16.3
CAN_2_P: J2.49 J16.2
CAN_3_N: J2.57
CAN_3_P: J2.59
CAN_JET_N: J2.43 J12.3 R4.1
CAN_JET_P: J2.41 J12.2 R4.2
CS0: J1.13 J10.3
CS1: J1.15 J10.2
CSI0_CLK_N: J1.108 J4.15
CSI0_CLK_P: J1.106 J4.14
CSI0_D0_N: J1.116 J4.21
CSI0_D0_P: J1.114 J4.20
CSI0_D1_N: J1.102 J4.18
CSI0_D1_P: J1.100 J4.17
CSI1_CLK_N: J1.107 J5.15
CSI1_CLK_P: J1.105 J5.14
CSI1_D0_N: J1.115 J5.21
CSI1_D0_P: J1.113 J5.20
CSI1_D1_N: J1.101 J5.18
CSI1_D1_P: J1.99 J5.17
CSI2_CLK_N: J1.88 J7.15
CSI2_CLK_P: J1.86 J7.14
CSI2_D0_N: J1.96 J7.21
CSI2_D0_P: J1.94 J7.20
CSI2_D1_N: J1.82 J7.18
CSI2_D1_P: J1.80 J7.17
CSI3_CLK_N: J1.87
CSI3_CLK_P: J1.85
CSI3_D0_N: J1.95 J7.12
CSI3_D0_P: J1.93 J7.11
CSI3_D1_N: J1.81 J7.9
CSI3_D1_P: J1.79 J7.8
ETH1A_N: J2.89 J3.11
ETH1A_P: J2.85 J3.10
ETH1B_N: J2.99 J3.8
ETH1B_P: J2.95 J3.7
ETH1C_N: J2.107 J3.5
ETH1C_P: J2.103 J3.4
ETH1D_N: J2.117 J3.2
ETH1D_P: J2.113 J3.1
ETH2A_N: J2.90 J6.11
ETH2A_P: J2.86 J6.10
ETH2B_N: J2.100 J6.8
ETH2B_P: J2.96 J6.7
ETH2C_N: J2.108 J6.5
ETH2C_P: J2.104 J6.4
ETH2D_N: J2.118 J6.2
ETH2D_P: J2.114 J6.1
EXT_USB0_VBUS: J1.5
FMU_BAT_I_SENSE: J2.27 J8.4
FMU_BAT_V_SENSE: J2.25 J8.3
FMU_CH1: J2.42
FMU_CH2: J2.44
FMU_CH3: J2.46
FMU_CH4: J2.48
FMU_CH5: J2.50
FMU_CH6: J2.52
FMU_DRDY: J2.26
FMU_SAFETY_SIG: J2.70 J21.6
GND: C8.2 C9.- C10.2 C11.- C12.2 C13.- FC1.GND FC2.GND FC3.GND FC4.GND FC5.GND FC6.GND FC7.GND FC8.GND FC9.GND FC10.GND IC4.5 IC4.7 IC5.5 IC5.7 IC6.5 IC6.7 J1.1 J1.2 J1.3 J1.8 J1.14 J1.20 J1.26 J1.32 J1.38 J1.44 J1.50 J1.51 J1.57 J1.60 J1.63 J1.66 J1.69 J1.72 J1.77 J1.78 J1.83 J1.84 J1.89 J1.90 J1.91 J1.92 J1.97 J1.98 J1.103 J1.104 J1.109 J1.110 J1.111 J1.112 J1.117 J1.118 J1.MP1 J1.MP2 J1.MP3 J1.MP4 J1.MP5 J1.MP6 J1.MP7 J1.MP8 J1.MP9 J1.MP10 J1.MP11 J1.MP12 J1.MP13 J1.MP14 J2.45 J2.55 J2.87 J2.88 J2.93 J2.94 J2.97 J2.98 J2.101 J2.102 J2.105 J2.106 J2.109 J2.110 J2.111 J2.112 J2.115 J2.116 J2.119 J2.120 J2.MP1 J2.MP2 J2.MP3 J2.MP4 J2.MP5 J2.MP6 J2.MP7 J2.MP8 J2.MP9 J2.MP10 J2.MP11 J2.MP12 J2.MP13 J2.MP14 J3.3 J3.6 J3.9 J3.12 J3.MP1 J3.MP2 J4.4 J4.7 J4.10 J4.13 J4.16 J4.19 J4.22 J4.MP1 J4.MP2 J4.MP3 J4.MP4 J5.4 J5.7 J5.10 J5.13 J5.16 J5.19 J5.22 J5.MP1 J5.MP2 J5.MP3 J5.MP4 J6.3 J6.6 J6.9 J6.12 J6.MP1 J6.MP2 J7.4 J7.7 J7.10 J7.13 J7.16 J7.19 J7.22 J7.MP1 J7.MP2 J7.MP3 J7.MP4 J8.5 J8.6 J8.GND J9.1 J9.4 J9.7 J9.10 J9.12 J9.MP1 J9.MP2 J9.MP3 J9.MP4 J9.MP5 J9.MP6 J10.8 J10.GND J11.6 J12.4 J12.GND J13.1 J13.4 J13.7 J13.10 J13.11 J13.MP1 J13.MP2 J13.MP3 J13.MP4 J14.1 J14.4 J14.7 J14.10 J14.11 J14.MP1 J14.MP2 J14.MP3 J14.MP4 J15.1 J15.4 J15.7 J15.10 J15.11 J15.MP2 J15.MP4 J16.4 J16.GND J17.4 J17.GND J18.6 J18.GND J19.4 J19.GND J20.8 J20.GND J21.8 J21.GND J22.6 J22.GND J23.6 J23.GND J26.07 J26.08 J28.3 J28.MP R5.1 R6.1 R7.1 | length 1.6
  Layer 2 w0.254: 15.575,40.5 cw(c15.575,38.569) 16.941,39.934 17,39.875
  other v1: 43.65,3.225 33.7,4.925 36.2,4.925 33.7,6.55 36.2,6.55 19.2,7.15 31.6,21.2 46.7,28.6 39.6,31.55 33.4,38.425
GPIO_EXP_0: J2.29 J4.6
GPIO_EXP_1: J2.31 J5.6
GPIO_EXP_2: J2.33 J7.6
GPIO_EXP_3: J2.35
GPIO_EXP_4: J2.37 J8.1
GPIO_EXP_5: J2.39 J8.2
I2C0_SCL: J1.33 J5.3 J11.4
I2C0_SDA: J1.35 J5.2 J11.5
I2C1_SCL: J1.37 J7.3
I2C1_SDA: J1.39 J7.2
I2C2_SCL: J1.41
I2C2_SDA: J1.43
I2C_FMU_1_SCL: J2.78 J21.4
I2C_FMU_1_SDA: J2.80 J21.5
I2C_FMU_2_SCL: J2.82 J17.2 J18.4
I2C_FMU_2_SDA: J2.84 J17.3 J18.5
I2S_JET_DIN: J1.19
I2S_JET_DOUT: J1.17
I2S_JET_FS: J1.21
I2S_JET_SCLK: J1.23
I\O\-\L\E\D\_\S\A\F\E\T\_\P\R\O\T\: J2.74 J21.7
IO_CH1: J2.68 J20.1
IO_CH2: J2.66 J20.2
IO_CH3: J2.64 J20.3
IO_CH4: J2.62 J20.4
IO_CH5: J2.60 J20.5
IO_CH6: J2.58 J20.6
IO_CH7: J2.56 J20.7
IO_CH8: J2.54
JET_PWM_OUT_1: J1.71 J4.5 J5.5 J7.5
JET_PWM_OUT_2: J1.73
MISO: J1.11 J10.4
MOSI: J1.7 J10.6
NetC9_+: C9.+ IC4.1 J13.12 J13.13 J13.14 J13.15
NetC11_+: C11.+ IC5.1 J14.12 J14.13 J14.14 J14.15
NetFC1_2: FC1.2 J10.1
NetFC2_2: FC2.2 J11.1
NetFC3_2: FC3.2 J12.1
NetFC4_2: FC4.2 J16.1
NetFC5_2: FC5.2 J17.1
NetFC6_2: FC6.2 J18.1
NetFC7_2: FC7.2 J19.1
NetFC8_2: FC8.2 J21.1
NetFC9_2: FC9.2 J22.1
NetFC10_2: FC10.2 J23.1
NetIC4_2: IC4.2 R5.2
NetIC5_2: IC5.2 R6.2
NetJ1_4: J1.4
NetJ1_6: J1.6
NetJ2_9: J2.9 J2.11 J2.13 J2.15
NetJ2_40: J2.40
NetJ15_MP1: J15.MP1 J15.MP3
NetJ28_1: J28.1
NetJ28_2: J28.2
NetJ28_4: J28.4
NetJ28_5: J28.5
NetJ28_6: J28.6
NetJ28_7: J28.7
NetJ28_8: J28.8
NetJ28_9: J28.9
NetJ28_10: J28.10
NetJ28_11: J28.11
NetJ28_12: J28.12
NetJ28_13: J28.13
NetJ28_14: J28.14
NetJ28_16: J28.16
NetJ28_17: J28.17
NetJ28_18: J28.18
NetJ28_19: J28.19
NetJ28_20: J28.20
nPCIE_CLKREQ: J1.45 J9.14
nPCIE_RST: J1.47 J9.13
nPCIE_WAKE: J1.49 J9.15
PCIE_AD_CLK_N: J1.55 J9.9
PCIE_AD_CLK_P: J1.53 J9.8
PCIE_AD_RX_N: J1.67 J9.6
PCIE_AD_RX_P: J1.65 J9.5
PCIE_AD_TX_N: J1.61 J9.3
PCIE_AD_TX_P: J1.59 J9.2
PRESS_SENSE: J2.76
SBUS_OUT: J2.72 J22.4
SCK: J1.9 J10.5
SERIAL1_CTS: J2.79 J23.4
SERIAL1_RTS: J2.77 J23.5
SERIAL1_RX: J2.73 J23.3
SERIAL1_TX: J2.75 J23.2
SERIAL3_RX: J2.63 J21.3
SERIAL3_TX: J2.61 J21.2
SERIAL4_RX: J2.67 J18.3
SERIAL4_TX: J2.65 J18.2
SERIAL5_RX: J2.71 J22.3
SERIAL5_TX: J2.69 J22.2
SERIAL8_RX: J2.81
SERIAL8_TX: J2.83
UART_JET_RX: J1.27 J11.3
UART_JET_TX: J1.25 J11.2
USB_0_N: J1.18 J13.8
USB_0_OCS: IC4.3 J1.10
USB_0_P: J1.16 J13.9
USB_0_PWR: IC4.4 J1.12
USB_1_N: J1.64 J14.8
USB_1_OCS: IC5.3 J1.56
USB_1_P: J1.62 J14.9
USB_1_PWR: IC5.4 J1.58
USB_2_N: J1.48 J15.8
USB_2_OCS: C13.+ IC6.1 IC6.2 IC6.3 J1.52 J15.12 J15.13 J15.14 J15.15 R7.2
USB_2_P: J1.46 J15.9
USB_2_PWR: IC6.4 J1.54
USBSS0_RX_N: J1.30 J13.2
USBSS0_RX_P: J1.28 J13.3
USBSS0_TX_N: J1.24 J13.5
USBSS0_TX_P: J1.22 J13.6
USBSS1_RX_N: J1.76 J14.2
USBSS1_RX_P: J1.74 J14.3
USBSS1_TX_N: J1.70 J14.5
USBSS1_TX_P: J1.68 J14.6
USBSS2_RX_N: J1.42 J15.2
USBSS2_RX_P: J1.40 J15.3
USBSS2_TX_N: J1.36 J15.5
USBSS2_TX_P: J1.34 J15.6
VDD_SOM: J26.04
pads on no net: J1. J2. J2.1 J2.2 J2.3 J2.4 J2.5 J2.6 J2.7 J2.8 J2.10 J2.12 J2.14 J2.16 J2.17 J2.18 J2.19 J2.20 J2.21 J2.22 J2.23 J2.91 J2.92 J3.13 J3.14 J4.8 J4.9 J4.11 J4.12 J5.8 J5.9 J5.11 J5.12 J6.13 J6.14 J9.11 J10.7 J11.GND J22.5 J26.05 J26.S1 J26.S2 J26.S3 J26.S4 J28.15 J28.LOC

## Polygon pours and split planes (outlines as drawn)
GND on Layer 2 "NONET_L-01_P-001" (solid, remove dead copper, shelved, pour order 4): 0,51 0,0 46,0 46,51
GND on Layer 5 "NONET_L-01_P-001" (solid, remove dead copper, shelved, pour order 6): 0,51 0,0 46,0 46,51
GND on Bottom Layer "NONET_L-01_P-001" (solid, remove dead copper, shelved, pour order 5): 0,51 46,51 46,0 0,0
GND on Top Layer "NONET_L-01_P-001" (solid, remove dead copper, shelved, pour order 7): 0,51 0,0 46,0 46,51

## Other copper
Bottom Layer:
  region net 5V_PERIPH: 36.05,10.15 39.525,10.15 39.525,10.825 40.05,11.35 40.925,11.35 41.3,10.975 41.275,10.95 41.275,10.15 42.925,10.15 42.925,12.25 36.05,12.25
  text ".gYear" at 9.05,1.65 h0.7
  text ".gRevision" at 14.65,1.65 h0.7
Multi-Layer:
  lines w0.1: 119.5,1 cw(c118.5,1) 118.5,0 ccw(c118.5,1) 119.5,1 ; 119.5,1 119.5,50 ; 119.5,1 119.5,50 ; 119.5,50 ccw(c118.5,50) 118.5,51 cw(c118.5,50) 119.5,50

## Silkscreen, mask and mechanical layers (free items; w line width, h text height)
Board Shape:
  lines w0.1: 2.45,5.598 2.45,45.4 ccw(c1.95,45.4) 1.95,45.9 0.45,45.9 cw(c0.45,46.4) -0.05,46.4 ; 2.45,5.6 cw(c1.95,5.6) 1.95,5.1 0.45,5.1 ccw(c0.45,4.6) -0.05,4.6 -0.05,0.5 ; -0.05,0.5 ccw(c0.45,0.5) 0.45,0 ; -0.05,0.5 ccw(c0.45,0.5) 0.45,0 ; -0.05,46.4 -0.05,50.5 ; -0.05,46.4 -0.05,50.5 ; -0.05,50.5 cw(c0.45,50.5) 0.45,51 ; -0.05,50.5 cw(c0.45,50.5) 0.45,51 ; 0.45,0 118.5,0 ccw(c118.5,1) 119.5,1 119.5,50 ccw(c118.5,50) 118.5,51 1.95,51 ; 0.45,51 1.95,51 ; 0.45,51 1.95,51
